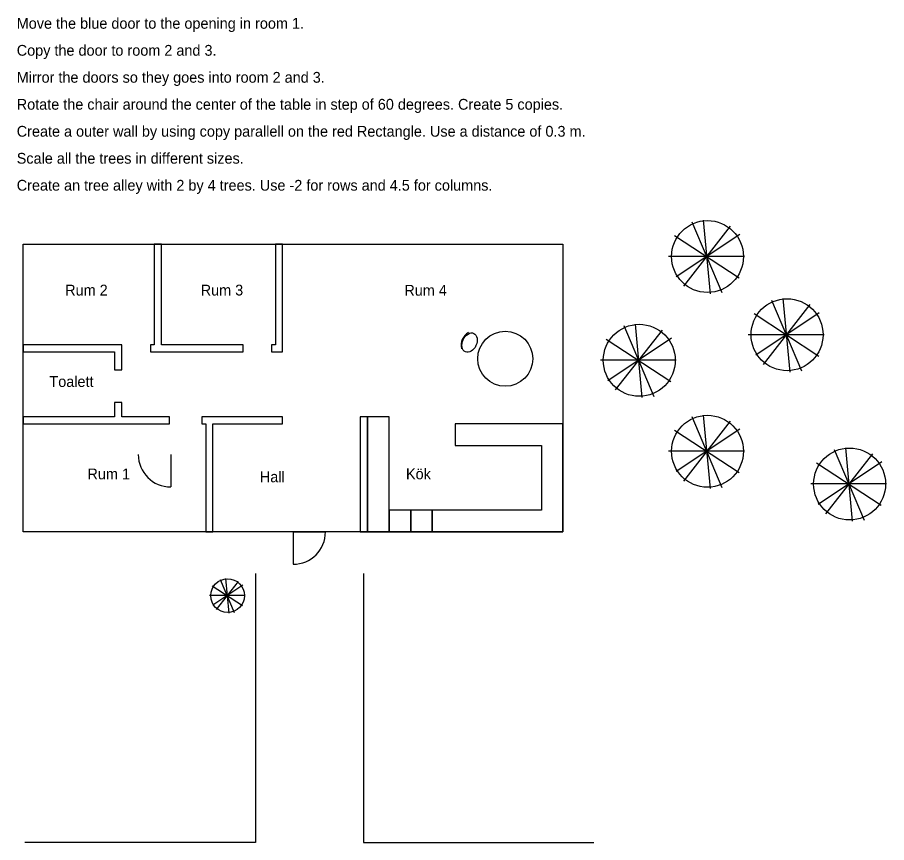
# Model space of a CAD drawing. Extents: x 1517703.8 to 1517728, y 6495353.2 to 6495376.2.
import ezdxf

# ---------------------------------------------------------------- set-up
doc = ezdxf.new("R2010")
doc.units = 0
doc.layers.add('Instruktioner', color=7, linetype='Continuous')
doc.layers.add('Lager 1', color=7, linetype='Continuous')

msp = doc.modelspace()

# ---------------------------------------------------------------- linework, layer by layer
at = {"layer": 'Instruktioner'}
for p, q in [((1517707.802, 6495367.063), (1517707.802, 6495369.863)), ((1517707.602, 6495366.863), (1517707.802, 6495366.863)), ((1517709.234, 6495364.863), (1517711.17, 6495364.863)), ((1517718.362, 6495364.263), (1517718.362, 6495362.463)), ((1517711.462, 6495361.863), (1517712.362, 6495361.863)), ((1517711.462, 6495361.863), (1517711.462, 6495360.963)), ((1517710.417, 6495360.711), (1517710.417, 6495353.23)), ((1517713.415, 6495360.711), (1517713.415, 6495353.231)), ((1517710.416, 6495353.229), (1517704.007, 6495353.229)), ((1517713.416, 6495353.23), (1517719.825, 6495353.23))]:
    msp.add_line(p, q, dxfattribs=at)
for points in [[(1517707.802, 6495369.863), (1517707.602, 6495369.863), (1517707.602, 6495367.063)], [(1517710.97, 6495366.863), (1517711.17, 6495366.863), (1517711.17, 6495369.863), (1517710.97, 6495369.863), (1517710.97, 6495367.063)], [(1517706.702, 6495366.863), (1517706.702, 6495367.063), (1517703.962, 6495367.063), (1517703.962, 6495366.863), (1517706.502, 6495366.863)], [(1517707.602, 6495367.063), (1517707.497, 6495367.063), (1517707.497, 6495366.863), (1517707.602, 6495366.863)], [(1517707.802, 6495366.863), (1517710.07, 6495366.863), (1517710.07, 6495367.063), (1517707.802, 6495367.063)], [(1517710.97, 6495367.063), (1517710.865, 6495367.063), (1517710.865, 6495366.863), (1517710.97, 6495366.863)], [(1517706.502, 6495366.863), (1517706.502, 6495366.363), (1517706.702, 6495366.363), (1517706.702, 6495366.863)], [(1517706.702, 6495365.063), (1517706.702, 6495365.463), (1517706.502, 6495365.463), (1517706.502, 6495365.063)], [(1517706.502, 6495365.063), (1517703.962, 6495365.063), (1517703.962, 6495364.863), (1517708.028, 6495364.863), (1517708.028, 6495365.063), (1517706.702, 6495365.063)], [(1517709.034, 6495365.063), (1517708.928, 6495365.063), (1517708.928, 6495364.863), (1517709.034, 6495364.863)], [(1517711.17, 6495364.863), (1517711.17, 6495365.063), (1517709.034, 6495365.063)], [(1517709.034, 6495364.863), (1517709.034, 6495361.863), (1517709.234, 6495361.863), (1517709.234, 6495364.863)], [(1517718.962, 6495364.263), (1517718.962, 6495364.863), (1517715.962, 6495364.863), (1517715.962, 6495364.263), (1517718.362, 6495364.263)], [(1517718.362, 6495361.863), (1517718.962, 6495361.863), (1517718.962, 6495364.263)], [(1517718.362, 6495362.463), (1517715.33, 6495362.463), (1517715.33, 6495361.863), (1517718.362, 6495361.863)]]:
    msp.add_lwpolyline(points, dxfattribs=at)
for points in [[(1517713.33, 6495361.863), (1517713.53, 6495361.863), (1517713.53, 6495365.063), (1517713.33, 6495365.063)], [(1517714.13, 6495365.063), (1517713.53, 6495365.063), (1517713.53, 6495361.863), (1517714.13, 6495361.863)], [(1517714.73, 6495362.463), (1517714.13, 6495362.463), (1517714.13, 6495361.863), (1517714.73, 6495361.863)], [(1517715.33, 6495362.463), (1517714.73, 6495362.463), (1517714.73, 6495361.863), (1517715.33, 6495361.863)]]:
    msp.add_lwpolyline(points, close=True, dxfattribs=at)
msp.add_circle((1517717.358, 6495366.675), 0.765, dxfattribs=at)
for centre, radius, start, end in [((1517711.462, 6495361.863), 0.9, 270, 0), ((1517710.416, 6495353.23), 0.001, 270, 0), ((1517713.416, 6495353.231), 0.001, 180, 270)]:
    msp.add_arc(centre, radius, start, end, dxfattribs=at)
at = {"layer": 'Lager 1'}
for p, q in [((1517723.614, 6495370.357), (1517722.311, 6495368.691)), ((1517722.548, 6495370.479), (1517723.381, 6495368.514)), ((1517722.863, 6495370.523), (1517723.053, 6495368.48)), ((1517722.061, 6495370.104), (1517723.859, 6495368.923)), ((1517723.874, 6495370.128), (1517722.108, 6495368.95)), ((1517724.009, 6495369.516), (1517721.899, 6495369.516)), ((1517725.826, 6495368.184), (1517724.523, 6495366.518)), ((1517724.76, 6495368.306), (1517725.593, 6495366.341)), ((1517725.074, 6495368.35), (1517725.264, 6495366.307)), ((1517724.273, 6495367.931), (1517726.071, 6495366.75)), ((1517726.086, 6495367.955), (1517724.319, 6495366.777)), ((1517720.967, 6495367.639), (1517721.157, 6495365.596)), ((1517721.718, 6495367.473), (1517720.415, 6495365.807)), ((1517720.653, 6495367.595), (1517721.485, 6495365.63)), ((1517720.165, 6495367.22), (1517721.963, 6495366.039)), ((1517721.978, 6495367.244), (1517720.212, 6495366.066)), ((1517726.221, 6495367.343), (1517724.111, 6495367.343)), ((1517722.113, 6495366.632), (1517720.003, 6495366.632)), ((1517722.548, 6495365.066), (1517723.381, 6495363.101)), ((1517722.863, 6495365.111), (1517723.053, 6495363.067)), ((1517723.614, 6495364.945), (1517722.311, 6495363.278)), ((1517722.061, 6495364.692), (1517723.859, 6495363.511)), ((1517723.874, 6495364.716), (1517722.108, 6495363.538)), ((1517708.06, 6495364.013), (1517708.06, 6495363.113)), ((1517724.009, 6495364.104), (1517721.899, 6495364.104)), ((1517727.563, 6495364.036), (1517726.26, 6495362.37)), ((1517726.498, 6495364.158), (1517727.33, 6495362.193)), ((1517726.812, 6495364.202), (1517727.002, 6495362.158)), ((1517726.01, 6495363.783), (1517727.808, 6495362.602)), ((1517727.824, 6495363.807), (1517726.057, 6495362.629)), ((1517727.958, 6495363.195), (1517725.848, 6495363.195)), ((1517709.938, 6495360.487), (1517709.327, 6495359.706)), ((1517709.438, 6495360.543), (1517709.828, 6495359.623)), ((1517709.586, 6495360.564), (1517709.675, 6495359.607)), ((1517709.21, 6495360.368), (1517710.052, 6495359.815)), ((1517710.06, 6495360.379), (1517709.232, 6495359.827)), ((1517710.123, 6495360.092), (1517709.134, 6495360.092))]:
    msp.add_line(p, q, dxfattribs=at)
msp.add_lwpolyline([(1517703.962, 6495369.863), (1517718.962, 6495369.863), (1517718.962, 6495361.863), (1517703.962, 6495361.863)], close=True, dxfattribs=at)
for centre, radius in [((1517722.98, 6495369.516), 1), ((1517725.191, 6495367.343), 1), ((1517721.084, 6495366.632), 1), ((1517722.98, 6495364.104), 1), ((1517726.929, 6495363.195), 1), ((1517709.641, 6495360.092), 0.469)]:
    msp.add_circle(centre, radius, dxfattribs=at)
for centre, radius, start, end in [((1517716.526, 6495367.05), 0.398, 118.1196, 193.9418), ((1517708.06, 6495364.013), 0.9, 180, 270)]:
    msp.add_arc(centre, radius, start, end, dxfattribs=at)
msp.add_ellipse((1517716.367, 6495367.123), major_axis=(0.117, 0.258), ratio=0.690069, dxfattribs=at)

# ---------------------------------------------------------------- texts
at = {"layer": 'Instruktioner'}
for s, p in [('Move the blue door to the opening in room 1.', (1517703.78, 6495375.846)), ('Copy the door to room 2 and 3.', (1517703.78, 6495375.096)), ('Mirror the doors so they goes into room 2 and 3.', (1517703.78, 6495374.346)), ('Rotate the chair around the center of the table in step of 60 degrees. Create 5 copies.', (1517703.78, 6495373.596)), ('Create a outer wall by using copy parallell on the red Rectangle. Use a distance of 0.3 m.', (1517703.78, 6495372.846)), ('Scale all the trees in different sizes.', (1517703.78, 6495372.096)), ('Create an tree alley with 2 by 4 trees. Use -2 for rows and 4.5 for columns.', (1517703.78, 6495371.346)), ('Rum 2', (1517705.127, 6495368.433)), ('Rum 3', (1517708.893, 6495368.433)), ('Rum 4', (1517714.554, 6495368.428)), ('Toalett', (1517704.688, 6495365.892)), ('Rum 1', (1517705.746, 6495363.324)), ('Hall', (1517710.537, 6495363.244)), ('Kök', (1517714.599, 6495363.326))]:
    msp.add_text(s, height=0.3, dxfattribs=at).set_placement(p)

doc.saveas('drawing.dxf')
